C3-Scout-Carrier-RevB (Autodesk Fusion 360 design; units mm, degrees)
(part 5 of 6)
work_plane "WorkPlane1" AlongDistance 0.1 ExtraOffset 0
sketch "Component body profile" plane through (0, 0, 0.1) normal (0, 0, 1) x axis (1, 0, 0)
  line L1 (2.25, -1.4) -> (-2.25, -1.4)
  line L2 (2.25, 1.4) -> (2.25, -1.4)
  line L3 (-2.25, 1.4) -> (2.25, 1.4)
  line L4 (-2.25, -1.4) -> (-2.25, 1.4)
extrude "Extrude1" new body sketch "Component body profile" along normal blind 1.9
sketch "Metallized terminations profiles" plane through (0, 0, 0) normal (0, 0, 1) x axis (1, 0, 0)
  line L1 (-1.65, -1.4) -> (-2.3, -1.4)
  line L2 (-1.65, 1.4) -> (-1.65, -1.4)
  line L3 (-2.3, 1.4) -> (-1.65, 1.4)
  line L4 (-2.3, -1.4) -> (-2.3, 1.4)
  line L5 (2.3, -1.4) -> (1.65, -1.4)
  line L6 (2.3, 1.4) -> (2.3, -1.4)
  line L7 (1.65, 1.4) -> (2.3, 1.4)
  line L8 (1.65, -1.4) -> (1.65, 1.4)
extrude "Extrude2" new body sketch "Metallized terminations profiles" along normal blind 0.5
work_plane "WorkPlane2" AlongDistance 2 ExtraOffset 0
sketch "Cathode band profiles" plane through (0, 0, 2) normal (0, 0, 1) x axis (1, 0, 0)
  line L1 (-1.35, -1.4) -> (-1.65, -1.4)
  line L2 (-1.35, 1.4) -> (-1.35, -1.4)
  line L3 (-1.65, 1.4) -> (-1.35, 1.4)
  line L4 (-1.65, -1.4) -> (-1.65, 1.4)
extrude "Extrude3" new body sketch "Cathode band profiles" along normal blind 0.012
work_plane "WorkPlane1" AlongDistance 0.1 ExtraOffset 0
sketch "Component body profile" plane through (0, 0, 0.1) normal (0, 0, 1) x axis (1, 0, 0)
  line L1 (1.6, -0.8) -> (-1.6, -0.8)
  line L2 (1.6, 0.8) -> (1.6, -0.8)
  line L3 (-1.6, 0.8) -> (1.6, 0.8)
  line L4 (-1.6, -0.8) -> (-1.6, 0.8)
extrude "Extrude1" new body sketch "Component body profile" along normal blind 0.6
sketch "Metallized terminations profiles" plane through (0, 0, 0) normal (0, 0, 1) x axis (1, 0, 0)
  line L1 (-1.25, -0.8) -> (-1.65, -0.8)
  line L2 (-1.25, 0.8) -> (-1.25, -0.8)
  line L3 (-1.65, 0.8) -> (-1.25, 0.8)
  line L4 (-1.65, -0.8) -> (-1.65, 0.8)
  line L5 (1.65, -0.8) -> (1.25, -0.8)
  line L6 (1.65, 0.8) -> (1.65, -0.8)
  line L7 (1.25, 0.8) -> (1.65, 0.8)
  line L8 (1.25, -0.8) -> (1.25, 0.8)
extrude "Extrude2" new body sketch "Metallized terminations profiles" along normal blind 0.5
work_plane "WorkPlane1" AlongDistance 0.1 ExtraOffset 0
sketch "Component body profile" plane through (0, 0, 0.1) normal (0, 0, 1) x axis (1, 0, 0)
  line L1 (1.6, -0.8) -> (-1.6, -0.8)
  line L2 (1.6, 0.8) -> (1.6, -0.8)
  line L3 (-1.6, 0.8) -> (1.6, 0.8)
  line L4 (-1.6, -0.8) -> (-1.6, 0.8)
extrude "Extrude1" new body sketch "Component body profile" along normal blind 0.6
sketch "Metallized terminations profiles" plane through (0, 0, 0) normal (0, 0, 1) x axis (1, 0, 0)
  line L1 (-1.25, -0.8) -> (-1.65, -0.8)
  line L2 (-1.25, 0.8) -> (-1.25, -0.8)
  line L3 (-1.65, 0.8) -> (-1.25, 0.8)
  line L4 (-1.65, -0.8) -> (-1.65, 0.8)
  line L5 (1.65, -0.8) -> (1.25, -0.8)
  line L6 (1.65, 0.8) -> (1.65, -0.8)
  line L7 (1.25, 0.8) -> (1.65, 0.8)
  line L8 (1.25, -0.8) -> (1.25, 0.8)
extrude "Extrude2" new body sketch "Metallized terminations profiles" along normal blind 0.5
work_plane "WorkPlane1" AlongDistance 0.1 ExtraOffset 0
sketch "Component body profile" plane through (0, 0, 0.1) normal (0, 0, 1) x axis (1, 0, 0)
  line L1 (1.6, -0.8) -> (-1.6, -0.8)
  line L2 (1.6, 0.8) -> (1.6, -0.8)
  line L3 (-1.6, 0.8) -> (1.6, 0.8)
  line L4 (-1.6, -0.8) -> (-1.6, 0.8)
extrude "Extrude1" new body sketch "Component body profile" along normal blind 0.6
sketch "Metallized terminations profiles" plane through (0, 0, 0) normal (0, 0, 1) x axis (1, 0, 0)
  line L1 (-1.25, -0.8) -> (-1.65, -0.8)
  line L2 (-1.25, 0.8) -> (-1.25, -0.8)
  line L3 (-1.65, 0.8) -> (-1.25, 0.8)
  line L4 (-1.65, -0.8) -> (-1.65, 0.8)
  line L5 (1.65, -0.8) -> (1.25, -0.8)
  line L6 (1.65, 0.8) -> (1.65, -0.8)
  line L7 (1.25, 0.8) -> (1.65, 0.8)
  line L8 (1.25, -0.8) -> (1.25, 0.8)
extrude "Extrude2" new body sketch "Metallized terminations profiles" along normal blind 0.5
work_plane "WorkPlane1" AlongDistance 0.1 ExtraOffset 0
sketch "Component body profile" plane through (0, 0, 0.1) normal (0, 0, 1) x axis (1, 0, 0)
  line L1 (1, -0.625) -> (-1, -0.625)
  line L2 (1, 0.625) -> (1, -0.625)
  line L3 (-1, 0.625) -> (1, 0.625)
  line L4 (-1, -0.625) -> (-1, 0.625)
extrude "Extrude1" new body sketch "Component body profile" along normal blind 0.6
sketch "Metallized terminations profiles" plane through (0, 0, 0) normal (0, 0, 1) x axis (1, 0, 0)
  line L1 (-0.65, -0.625) -> (-1.05, -0.625)
  line L2 (-0.65, 0.625) -> (-0.65, -0.625)
  line L3 (-1.05, 0.625) -> (-0.65, 0.625)
  line L4 (-1.05, -0.625) -> (-1.05, 0.625)
  line L5 (1.05, -0.625) -> (0.65, -0.625)
  line L6 (1.05, 0.625) -> (1.05, -0.625)
  line L7 (0.65, 0.625) -> (1.05, 0.625)
  line L8 (0.65, -0.625) -> (0.65, 0.625)
extrude "Extrude2" new body sketch "Metallized terminations profiles" along normal blind 0.5
work_plane "WorkPlane1" AlongDistance 0.1 ExtraOffset 0
sketch "Component body profile" plane through (0, 0, 0.1) normal (0, 0, 1) x axis (1, 0, 0)
  line L1 (1, -0.625) -> (-1, -0.625)
  line L2 (1, 0.625) -> (1, -0.625)
  line L3 (-1, 0.625) -> (1, 0.625)
  line L4 (-1, -0.625) -> (-1, 0.625)
extrude "Extrude1" new body sketch "Component body profile" along normal blind 0.6
sketch "Metallized terminations profiles" plane through (0, 0, 0) normal (0, 0, 1) x axis (1, 0, 0)
  line L1 (-0.65, -0.625) -> (-1.05, -0.625)
  line L2 (-0.65, 0.625) -> (-0.65, -0.625)
  line L3 (-1.05, 0.625) -> (-0.65, 0.625)
  line L4 (-1.05, -0.625) -> (-1.05, 0.625)
  line L5 (1.05, -0.625) -> (0.65, -0.625)
  line L6 (1.05, 0.625) -> (1.05, -0.625)
  line L7 (0.65, 0.625) -> (1.05, 0.625)
  line L8 (0.65, -0.625) -> (0.65, 0.625)
extrude "Extrude2" new body sketch "Metallized terminations profiles" along normal blind 0.5
work_plane "WorkPlane1" AlongDistance 0.1 ExtraOffset 0
sketch "Component body profile" plane through (0, 0, 0.1) normal (0, 0, 1) x axis (1, 0, 0)
  line L1 (1, -0.625) -> (-1, -0.625)
  line L2 (1, 0.625) -> (1, -0.625)
  line L3 (-1, 0.625) -> (1, 0.625)
  line L4 (-1, -0.625) -> (-1, 0.625)
extrude "Extrude1" new body sketch "Component body profile" along normal blind 0.6
sketch "Metallized terminations profiles" plane through (0, 0, 0) normal (0, 0, 1) x axis (1, 0, 0)
  line L1 (-0.65, -0.625) -> (-1.05, -0.625)
  line L2 (-0.65, 0.625) -> (-0.65, -0.625)
  line L3 (-1.05, 0.625) -> (-0.65, 0.625)
  line L4 (-1.05, -0.625) -> (-1.05, 0.625)
  line L5 (1.05, -0.625) -> (0.65, -0.625)
  line L6 (1.05, 0.625) -> (1.05, -0.625)
  line L7 (0.65, 0.625) -> (1.05, 0.625)
  line L8 (0.65, -0.625) -> (0.65, 0.625)
extrude "Extrude2" new body sketch "Metallized terminations profiles" along normal blind 0.5
work_plane "WorkPlane1" AlongDistance 0.1 ExtraOffset 0
sketch "Component body profile" plane through (0, 0, 0.1) normal (0, 0, 1) x axis (1, 0, 0)
  line L1 (1, -0.625) -> (-1, -0.625)
  line L2 (1, 0.625) -> (1, -0.625)
  line L3 (-1, 0.625) -> (1, 0.625)
  line L4 (-1, -0.625) -> (-1, 0.625)
extrude "Extrude1" new body sketch "Component body profile" along normal blind 0.6
sketch "Metallized terminations profiles" plane through (0, 0, 0) normal (0, 0, 1) x axis (1, 0, 0)
  line L1 (-0.65, -0.625) -> (-1.05, -0.625)
  line L2 (-0.65, 0.625) -> (-0.65, -0.625)
  line L3 (-1.05, 0.625) -> (-0.65, 0.625)
  line L4 (-1.05, -0.625) -> (-1.05, 0.625)
  line L5 (1.05, -0.625) -> (0.65, -0.625)
  line L6 (1.05, 0.625) -> (1.05, -0.625)
  line L7 (0.65, 0.625) -> (1.05, 0.625)
  line L8 (0.65, -0.625) -> (0.65, 0.625)
extrude "Extrude2" new body sketch "Metallized terminations profiles" along normal blind 0.5
work_plane "WorkPlane1" AlongDistance 0.1 ExtraOffset 0
sketch "Component body profile" plane through (0, 0, 0.1) normal (0, 0, 1) x axis (1, 0, 0)
  line L1 (1, -0.625) -> (-1, -0.625)
  line L2 (1, 0.625) -> (1, -0.625)
  line L3 (-1, 0.625) -> (1, 0.625)
  line L4 (-1, -0.625) -> (-1, 0.625)
extrude "Extrude1" new body sketch "Component body profile" along normal blind 0.6
sketch "Metallized terminations profiles" plane through (0, 0, 0) normal (0, 0, 1) x axis (1, 0, 0)
  line L1 (-0.65, -0.625) -> (-1.05, -0.625)
  line L2 (-0.65, 0.625) -> (-0.65, -0.625)
  line L3 (-1.05, 0.625) -> (-0.65, 0.625)
  line L4 (-1.05, -0.625) -> (-1.05, 0.625)
  line L5 (1.05, -0.625) -> (0.65, -0.625)
  line L6 (1.05, 0.625) -> (1.05, -0.625)
  line L7 (0.65, 0.625) -> (1.05, 0.625)
  line L8 (0.65, -0.625) -> (0.65, 0.625)
extrude "Extrude2" new body sketch "Metallized terminations profiles" along normal blind 0.5
work_plane "WorkPlane1" AlongDistance 0.1 ExtraOffset 0
sketch "Component body profile" plane through (0, 0, 0.1) normal (0, 0, 1) x axis (1, 0, 0)
  line L1 (1, -0.625) -> (-1, -0.625)
  line L2 (1, 0.625) -> (1, -0.625)
  line L3 (-1, 0.625) -> (1, 0.625)
  line L4 (-1, -0.625) -> (-1, 0.625)
extrude "Extrude1" new body sketch "Component body profile" along normal blind 0.6
sketch "Metallized terminations profiles" plane through (0, 0, 0) normal (0, 0, 1) x axis (1, 0, 0)
  line L1 (-0.65, -0.625) -> (-1.05, -0.625)
  line L2 (-0.65, 0.625) -> (-0.65, -0.625)
  line L3 (-1.05, 0.625) -> (-0.65, 0.625)
  line L4 (-1.05, -0.625) -> (-1.05, 0.625)
  line L5 (1.05, -0.625) -> (0.65, -0.625)
  line L6 (1.05, 0.625) -> (1.05, -0.625)
  line L7 (0.65, 0.625) -> (1.05, 0.625)
  line L8 (0.65, -0.625) -> (0.65, 0.625)
extrude "Extrude2" new body sketch "Metallized terminations profiles" along normal blind 0.5
work_plane "WorkPlane1" AlongDistance 0.1 ExtraOffset 0
sketch "Component body profile" plane through (0, 0, 0.1) normal (0, 0, 1) x axis (1, 0, 0)
  line L1 (1, -0.625) -> (-1, -0.625)
  line L2 (1, 0.625) -> (1, -0.625)
  line L3 (-1, 0.625) -> (1, 0.625)
  line L4 (-1, -0.625) -> (-1, 0.625)
extrude "Extrude1" new body sketch "Component body profile" along normal blind 0.6
sketch "Metallized terminations profiles" plane through (0, 0, 0) normal (0, 0, 1) x axis (1, 0, 0)
  line L1 (-0.65, -0.625) -> (-1.05, -0.625)
  line L2 (-0.65, 0.625) -> (-0.65, -0.625)
  line L3 (-1.05, 0.625) -> (-0.65, 0.625)
  line L4 (-1.05, -0.625) -> (-1.05, 0.625)
  line L5 (1.05, -0.625) -> (0.65, -0.625)
  line L6 (1.05, 0.625) -> (1.05, -0.625)
  line L7 (0.65, 0.625) -> (1.05, 0.625)
  line L8 (0.65, -0.625) -> (0.65, 0.625)
extrude "Extrude2" new body sketch "Metallized terminations profiles" along normal blind 0.5
work_plane "WorkPlane1" AlongDistance 0.1 ExtraOffset 0
sketch "Component body profile" plane through (0, 0, 0.1) normal (0, 0, 1) x axis (1, 0, 0)
  line L1 (1, -0.625) -> (-1, -0.625)
  line L2 (1, 0.625) -> (1, -0.625)
  line L3 (-1, 0.625) -> (1, 0.625)
  line L4 (-1, -0.625) -> (-1, 0.625)
extrude "Extrude1" new body sketch "Component body profile" along normal blind 0.6
sketch "Metallized terminations profiles" plane through (0, 0, 0) normal (0, 0, 1) x axis (1, 0, 0)
  line L1 (-0.65, -0.625) -> (-1.05, -0.625)
  line L2 (-0.65, 0.625) -> (-0.65, -0.625)
  line L3 (-1.05, 0.625) -> (-0.65, 0.625)
  line L4 (-1.05, -0.625) -> (-1.05, 0.625)
  line L5 (1.05, -0.625) -> (0.65, -0.625)
  line L6 (1.05, 0.625) -> (1.05, -0.625)
  line L7 (0.65, 0.625) -> (1.05, 0.625)
  line L8 (0.65, -0.625) -> (0.65, 0.625)
extrude "Extrude2" new body sketch "Metallized terminations profiles" along normal blind 0.5
work_plane "WorkPlane1" AlongDistance 0.1 ExtraOffset 0
sketch "Component body profile" plane through (0, 0, 0.1) normal (0, 0, 1) x axis (1, 0, 0)
  line L1 (1, -0.625) -> (-1, -0.625)
  line L2 (1, 0.625) -> (1, -0.625)
  line L3 (-1, 0.625) -> (1, 0.625)
  line L4 (-1, -0.625) -> (-1, 0.625)
extrude "Extrude1" new body sketch "Component body profile" along normal blind 0.6
sketch "Metallized terminations profiles" plane through (0, 0, 0) normal (0, 0, 1) x axis (1, 0, 0)
  line L1 (-0.65, -0.625) -> (-1.05, -0.625)
  line L2 (-0.65, 0.625) -> (-0.65, -0.625)
  line L3 (-1.05, 0.625) -> (-0.65, 0.625)
  line L4 (-1.05, -0.625) -> (-1.05, 0.625)
  line L5 (1.05, -0.625) -> (0.65, -0.625)
  line L6 (1.05, 0.625) -> (1.05, -0.625)
  line L7 (0.65, 0.625) -> (1.05, 0.625)
  line L8 (0.65, -0.625) -> (0.65, 0.625)
extrude "Extrude2" new body sketch "Metallized terminations profiles" along normal blind 0.5
work_plane "WorkPlane1" AlongDistance 0.1 ExtraOffset 0
sketch "Component body profile" plane through (0, 0, 0.1) normal (0, 0, 1) x axis (1, 0, 0)
  line L1 (1, -0.625) -> (-1, -0.625)
  line L2 (1, 0.625) -> (1, -0.625)
  line L3 (-1, 0.625) -> (1, 0.625)
  line L4 (-1, -0.625) -> (-1, 0.625)
extrude "Extrude1" new body sketch "Component body profile" along normal blind 0.6
sketch "Metallized terminations profiles" plane through (0, 0, 0) normal (0, 0, 1) x axis (1, 0, 0)
  line L1 (-0.65, -0.625) -> (-1.05, -0.625)
  line L2 (-0.65, 0.625) -> (-0.65, -0.625)
  line L3 (-1.05, 0.625) -> (-0.65, 0.625)
  line L4 (-1.05, -0.625) -> (-1.05, 0.625)
  line L5 (1.05, -0.625) -> (0.65, -0.625)
  line L6 (1.05, 0.625) -> (1.05, -0.625)
  line L7 (0.65, 0.625) -> (1.05, 0.625)
  line L8 (0.65, -0.625) -> (0.65, 0.625)
extrude "Extrude2" new body sketch "Metallized terminations profiles" along normal blind 0.5
work_plane "WorkPlane1" AlongDistance 0.1 ExtraOffset 0
sketch "Component body profile" plane through (0, 0, 0.1) normal (0, 0, 1) x axis (1, 0, 0)
  line L1 (1, -0.625) -> (-1, -0.625)
  line L2 (1, 0.625) -> (1, -0.625)
  line L3 (-1, 0.625) -> (1, 0.625)
  line L4 (-1, -0.625) -> (-1, 0.625)
extrude "Extrude1" new body sketch "Component body profile" along normal blind 0.6
sketch "Metallized terminations profiles" plane through (0, 0, 0) normal (0, 0, 1) x axis (1, 0, 0)
  line L1 (-0.65, -0.625) -> (-1.05, -0.625)
  line L2 (-0.65, 0.625) -> (-0.65, -0.625)
  line L3 (-1.05, 0.625) -> (-0.65, 0.625)
  line L4 (-1.05, -0.625) -> (-1.05, 0.625)
  line L5 (1.05, -0.625) -> (0.65, -0.625)
  line L6 (1.05, 0.625) -> (1.05, -0.625)
  line L7 (0.65, 0.625) -> (1.05, 0.625)
  line L8 (0.65, -0.625) -> (0.65, 0.625)
extrude "Extrude2" new body sketch "Metallized terminations profiles" along normal blind 0.5
work_plane "WorkPlane1" AlongDistance 0.1 ExtraOffset 0
sketch "Component body profile" plane through (0, 0, 0.1) normal (0, 0, 1) x axis (1, 0, 0)
  line L1 (1, -0.625) -> (-1, -0.625)
  line L2 (1, 0.625) -> (1, -0.625)
  line L3 (-1, 0.625) -> (1, 0.625)
  line L4 (-1, -0.625) -> (-1, 0.625)
extrude "Extrude1" new body sketch "Component body profile" along normal blind 0.6
sketch "Metallized terminations profiles" plane through (0, 0, 0) normal (0, 0, 1) x axis (1, 0, 0)
  line L1 (-0.65, -0.625) -> (-1.05, -0.625)
  line L2 (-0.65, 0.625) -> (-0.65, -0.625)
  line L3 (-1.05, 0.625) -> (-0.65, 0.625)
  line L4 (-1.05, -0.625) -> (-1.05, 0.625)
  line L5 (1.05, -0.625) -> (0.65, -0.625)
  line L6 (1.05, 0.625) -> (1.05, -0.625)
  line L7 (0.65, 0.625) -> (1.05, 0.625)
  line L8 (0.65, -0.625) -> (0.65, 0.625)
extrude "Extrude2" new body sketch "Metallized terminations profiles" along normal blind 0.5
work_plane "WorkPlane1" AlongDistance 0.1 ExtraOffset 0
sketch "Component body profile" plane through (0, 0, 0.1) normal (0, 0, 1) x axis (1, 0, 0)
  line L1 (1, -0.625) -> (-1, -0.625)
  line L2 (1, 0.625) -> (1, -0.625)
  line L3 (-1, 0.625) -> (1, 0.625)
  line L4 (-1, -0.625) -> (-1, 0.625)
extrude "Extrude1" new body sketch "Component body profile" along normal blind 0.6
sketch "Metallized terminations profiles" plane through (0, 0, 0) normal (0, 0, 1) x axis (1, 0, 0)
  line L1 (-0.65, -0.625) -> (-1.05, -0.625)
  line L2 (-0.65, 0.625) -> (-0.65, -0.625)
  line L3 (-1.05, 0.625) -> (-0.65, 0.625)
  line L4 (-1.05, -0.625) -> (-1.05, 0.625)
  line L5 (1.05, -0.625) -> (0.65, -0.625)
  line L6 (1.05, 0.625) -> (1.05, -0.625)
  line L7 (0.65, 0.625) -> (1.05, 0.625)
  line L8 (0.65, -0.625) -> (0.65, 0.625)
extrude "Extrude2" new body sketch "Metallized terminations profiles" along normal blind 0.5
work_plane "WorkPlane1" AlongDistance 0.1 ExtraOffset 0
sketch "Component body profile" plane through (0, 0, 0.1) normal (0, 0, 1) x axis (1, 0, 0)
  line L1 (1, -0.625) -> (-1, -0.625)
  line L2 (1, 0.625) -> (1, -0.625)
  line L3 (-1, 0.625) -> (1, 0.625)
  line L4 (-1, -0.625) -> (-1, 0.625)
extrude "Extrude1" new body sketch "Component body profile" along normal blind 0.6
sketch "Metallized terminations profiles" plane through (0, 0, 0) normal (0, 0, 1) x axis (1, 0, 0)
  line L1 (-0.65, -0.625) -> (-1.05, -0.625)
  line L2 (-0.65, 0.625) -> (-0.65, -0.625)
  line L3 (-1.05, 0.625) -> (-0.65, 0.625)
  line L4 (-1.05, -0.625) -> (-1.05, 0.625)
  line L5 (1.05, -0.625) -> (0.65, -0.625)
  line L6 (1.05, 0.625) -> (1.05, -0.625)
  line L7 (0.65, 0.625) -> (1.05, 0.625)
  line L8 (0.65, -0.625) -> (0.65, 0.625)
extrude "Extrude2" new body sketch "Metallized terminations profiles" along normal blind 0.5
work_plane "WorkPlane1" AlongDistance 0.1 ExtraOffset 0
sketch "Component body profile" plane through (0, 0, 0.1) normal (0, 0, 1) x axis (1, 0, 0)
  line L1 (1, -0.625) -> (-1, -0.625)
  line L2 (1, 0.625) -> (1, -0.625)
  line L3 (-1, 0.625) -> (1, 0.625)
  line L4 (-1, -0.625) -> (-1, 0.625)
extrude "Extrude1" new body sketch "Component body profile" along normal blind 0.6
sketch "Metallized terminations profiles" plane through (0, 0, 0) normal (0, 0, 1) x axis (1, 0, 0)
  line L1 (-0.65, -0.625) -> (-1.05, -0.625)
  line L2 (-0.65, 0.625) -> (-0.65, -0.625)
  line L3 (-1.05, 0.625) -> (-0.65, 0.625)
  line L4 (-1.05, -0.625) -> (-1.05, 0.625)
  line L5 (1.05, -0.625) -> (0.65, -0.625)
  line L6 (1.05, 0.625) -> (1.05, -0.625)
  line L7 (0.65, 0.625) -> (1.05, 0.625)
  line L8 (0.65, -0.625) -> (0.65, 0.625)
extrude "Extrude2" new body sketch "Metallized terminations profiles" along normal blind 0.5
work_plane "WorkPlane1" AlongDistance 0.1 ExtraOffset 0
sketch "Component body profile" plane through (0, 0, 0.1) normal (0, 0, 1) x axis (1, 0, 0)
  line L1 (1, -0.625) -> (-1, -0.625)
  line L2 (1, 0.625) -> (1, -0.625)
  line L3 (-1, 0.625) -> (1, 0.625)
  line L4 (-1, -0.625) -> (-1, 0.625)
extrude "Extrude1" new body sketch "Component body profile" along normal blind 0.6
sketch "Metallized terminations profiles" plane through (0, 0, 0) normal (0, 0, 1) x axis (1, 0, 0)
  line L1 (-0.65, -0.625) -> (-1.05, -0.625)
  line L2 (-0.65, 0.625) -> (-0.65, -0.625)
  line L3 (-1.05, 0.625) -> (-0.65, 0.625)
  line L4 (-1.05, -0.625) -> (-1.05, 0.625)
  line L5 (1.05, -0.625) -> (0.65, -0.625)
  line L6 (1.05, 0.625) -> (1.05, -0.625)
  line L7 (0.65, 0.625) -> (1.05, 0.625)
  line L8 (0.65, -0.625) -> (0.65, 0.625)
extrude "Extrude2" new body sketch "Metallized terminations profiles" along normal blind 0.5
work_plane "WorkPlane1" AlongDistance 0.1 ExtraOffset 0
sketch "Component body profile" plane through (0, 0, 0.1) normal (0, 0, 1) x axis (1, 0, 0)
  line L1 (1.6, -0.8) -> (-1.6, -0.8)
  line L2 (1.6, 0.8) -> (1.6, -0.8)
  line L3 (-1.6, 0.8) -> (1.6, 0.8)
  line L4 (-1.6, -0.8) -> (-1.6, 0.8)
extrude "Extrude1" new body sketch "Component body profile" along normal blind 0.6
sketch "Metallized terminations profiles" plane through (0, 0, 0) normal (0, 0, 1) x axis (1, 0, 0)
  line L1 (-1.25, -0.8) -> (-1.65, -0.8)
  line L2 (-1.25, 0.8) -> (-1.25, -0.8)
  line L3 (-1.65, 0.8) -> (-1.25, 0.8)
  line L4 (-1.65, -0.8) -> (-1.65, 0.8)
  line L5 (1.65, -0.8) -> (1.25, -0.8)
  line L6 (1.65, 0.8) -> (1.65, -0.8)
  line L7 (1.25, 0.8) -> (1.65, 0.8)
  line L8 (1.25, -0.8) -> (1.25, 0.8)
extrude "Extrude2" new body sketch "Metallized terminations profiles" along normal blind 0.5
sketch "Header insulators profiles" plane through (0, 0, 0) normal (0, 0, 1) x axis (1, 0, 0)
  line L1 (-6.42, -10.16) -> (-8.82, -10.16)
  line L2 (-6.42, 10.16) -> (-6.42, -10.16)
  line L3 (-8.82, 10.16) -> (-6.42, 10.16)
  line L4 (-8.82, -10.16) -> (-8.82, 10.16)
  line L5 (8.82, -10.16) -> (6.42, -10.16)
  line L6 (8.82, 10.16) -> (8.82, -10.16)
  line L7 (6.42, 10.16) -> (8.82, 10.16)
  line L8 (6.42, -10.16) -> (6.42, 10.16)
extrude "Extrude1" new body sketch "Header insulators profiles" along normal blind 2.5
work_plane "WorkPlane1" AlongDistance -2 ExtraOffset 0
sketch "Sixteen soldered square pins profiles" plane through (0, 0, -2) normal (0, 0, 1) x axis (1, 0, 0)
  line L1 (-7.37, 8.64) -> (-7.87, 8.64)
  line L2 (-7.37, 9.14) -> (-7.37, 8.64)
  line L3 (-7.87, 9.14) -> (-7.37, 9.14)
  line L4 (-7.87, 8.64) -> (-7.87, 9.14)
  line L5 (-7.37, 6.1) -> (-7.87, 6.1)
  line L6 (-7.37, 6.6) -> (-7.37, 6.1)
  line L7 (-7.87, 6.6) -> (-7.37, 6.6)
  line L8 (-7.87, 6.1) -> (-7.87, 6.6)
  line L9 (-7.37, 3.56) -> (-7.87, 3.56)
  line L10 (-7.37, 4.06) -> (-7.37, 3.56)
  line L11 (-7.87, 4.06) -> (-7.37, 4.06)
  line L12 (-7.87, 3.56) -> (-7.87, 4.06)
  line L13 (-7.37, 1.02) -> (-7.87, 1.02)
  line L14 (-7.37, 1.52) -> (-7.37, 1.02)
  line L15 (-7.87, 1.52) -> (-7.37, 1.52)
  line L16 (-7.87, 1.02) -> (-7.87, 1.52)
  line L17 (-7.37, -1.52) -> (-7.87, -1.52)
  line L18 (-7.37, -1.02) -> (-7.37, -1.52)
  line L19 (-7.87, -1.02) -> (-7.37, -1.02)
  line L20 (-7.87, -1.52) -> (-7.87, -1.02)
  line L21 (-7.37, -4.06) -> (-7.87, -4.06)
  line L22 (-7.37, -3.56) -> (-7.37, -4.06)
  line L23 (-7.87, -3.56) -> (-7.37, -3.56)
  line L24 (-7.87, -4.06) -> (-7.87, -3.56)
  line L25 (-7.37, -6.6) -> (-7.87, -6.6)
  line L26 (-7.37, -6.1) -> (-7.37, -6.6)
  line L27 (-7.87, -6.1) -> (-7.37, -6.1)
  line L28 (-7.87, -6.6) -> (-7.87, -6.1)
  line L29 (-7.37, -9.14) -> (-7.87, -9.14)
  line L30 (-7.37, -8.64) -> (-7.37, -9.14)
  line L31 (-7.87, -8.64) -> (-7.37, -8.64)
  line L32 (-7.87, -9.14) -> (-7.87, -8.64)
  line L33 (7.87, 8.64) -> (7.37, 8.64)
  line L34 (7.87, 9.14) -> (7.87, 8.64)
  line L35 (7.37, 9.14) -> (7.87, 9.14)
  line L36 (7.37, 8.64) -> (7.37, 9.14)
  line L37 (7.87, 6.1) -> (7.37, 6.1)
  line L38 (7.87, 6.6) -> (7.87, 6.1)
  line L39 (7.37, 6.6) -> (7.87, 6.6)
  line L40 (7.37, 6.1) -> (7.37, 6.6)
  line L41 (7.87, 3.56) -> (7.37, 3.56)
  line L42 (7.87, 4.06) -> (7.87, 3.56)
  line L43 (7.37, 4.06) -> (7.87, 4.06)
  line L44 (7.37, 3.56) -> (7.37, 4.06)
  line L45 (7.87, 1.02) -> (7.37, 1.02)
  line L46 (7.87, 1.52) -> (7.87, 1.02)
  line L47 (7.37, 1.52) -> (7.87, 1.52)
  line L48 (7.37, 1.02) -> (7.37, 1.52)
  line L49 (7.87, -1.52) -> (7.37, -1.52)
  line L50 (7.87, -1.02) -> (7.87, -1.52)
  line L51 (7.37, -1.02) -> (7.87, -1.02)
  line L52 (7.37, -1.52) -> (7.37, -1.02)
  line L53 (7.87, -4.06) -> (7.37, -4.06)
  line L54 (7.87, -3.56) -> (7.87, -4.06)
  line L55 (7.37, -3.56) -> (7.87, -3.56)
  line L56 (7.37, -4.06) -> (7.37, -3.56)
  line L57 (7.87, -6.6) -> (7.37, -6.6)
  line L58 (7.87, -6.1) -> (7.87, -6.6)
  line L59 (7.37, -6.1) -> (7.87, -6.1)
  line L60 (7.37, -6.6) -> (7.37, -6.1)
  line L61 (7.87, -9.14) -> (7.37, -9.14)
  line L62 (7.87, -8.64) -> (7.87, -9.14)
  line L63 (7.37, -8.64) -> (7.87, -8.64)
  line L64 (7.37, -9.14) -> (7.37, -8.64)
extrude "Extrude2" new body sketch "Sixteen soldered square pins profiles" along normal blind 6.2
sketch "Chamfered adhesive foot outline" plane through (0, 0, 0) normal (0, 0, 1) x axis (1, 0, 0)
  line L1 (31, -1.8) -> (1, -1.8)
  line L2 (32, -0.8) -> (31, -1.8)
  line L3 (32, 0.8) -> (32, -0.8)
  line L4 (31, 1.8) -> (32, 0.8)
  line L5 (1, 1.8) -> (31, 1.8)
  line L6 (0, 0.8) -> (1, 1.8)
  line L7 (0, -0.8) -> (0, 0.8)
  line L8 (1, -1.8) -> (0, -0.8)
extrude "Extrude1" new body sketch "Chamfered adhesive foot outline" along normal blind 1.2
work_plane "WorkPlane1" AlongDistance 1.2 ExtraOffset 0
sketch "M2 support boss profile" plane through (0, 0, 1.2) normal (0, 0, 1) x axis (1, 0, 0)
  circle C1 centre (3, 0) radius 2.8
extrude "Extrude2" add sketch "M2 support boss profile" along normal blind 4.3
work_plane "WorkPlane2" AlongDistance 1.2 ExtraOffset 0
sketch "M2 support boss profile (1)" plane through (0, 0, 1.2) normal (0, 0, 1) x axis (1, 0, 0)
  circle C1 centre (29, 0) radius 2.8
extrude "Extrude3" add sketch "M2 support boss profile (1)" along normal blind 4.3
sketch "M2 screw pilot holes profile" plane through (0, 0, 0) normal (0, 0, 1) x axis (1, 0, 0)
  circle C1 centre (3, 0) radius 0.85
  circle C2 centre (29, 0) radius 0.85
extrude "Extrude4" cut sketch "M2 screw pilot holes profile" along normal blind 5.5
sketch "M2 screw shank profile" plane through (0, 0, 0) normal (0, 0, 1) x axis (1, 0, 0)
  circle C1 centre (3, 0) radius 0.85
extrude "Extrude1" new body sketch "M2 screw shank profile" along normal blind 5.2
work_plane "WorkPlane1" AlongDistance 5.2 ExtraOffset 0
sketch "M2 pan head profile" plane through (0, 0, 5.2) normal (0, 0, 1) x axis (1, 0, 0)
  circle C1 centre (3, 0) radius 1.8
extrude "Extrude2" new body sketch "M2 pan head profile" along normal blind 1.2
work_plane "WorkPlane2" AlongDistance 5.95 ExtraOffset 0
sketch "Driver slot profile" plane through (0, 0, 5.95) normal (0, 0, 1) x axis (1, 0, 0)
  line L1 (4.1, -0.25) -> (1.9, -0.25)
  line L2 (4.1, 0.25) -> (4.1, -0.25)
  line L3 (1.9, 0.25) -> (4.1, 0.25)
  line L4 (1.9, -0.25) -> (1.9, 0.25)
extrude "Extrude3" cut sketch "Driver slot profile" along normal blind 0.46
sketch "M2 screw shank profile (1)" plane through (0, 0, 0) normal (0, 0, 1) x axis (1, 0, 0)
  circle C1 centre (29, 0) radius 0.85
extrude "Extrude4" new body sketch "M2 screw shank profile (1)" along normal blind 5.2
work_plane "WorkPlane3" AlongDistance 5.2 ExtraOffset 0
sketch "M2 pan head profile (1)" plane through (0, 0, 5.2) normal (0, 0, 1) x axis (1, 0, 0)
  circle C1 centre (29, 0) radius 1.8
extrude "Extrude5" new body sketch "M2 pan head profile (1)" along normal blind 1.2
work_plane "WorkPlane4" AlongDistance 5.95 ExtraOffset 0
sketch "Driver slot profile (1)" plane through (0, 0, 5.95) normal (0, 0, 1) x axis (1, 0, 0)
  line L1 (30.1, -0.25) -> (27.9, -0.25)
  line L2 (30.1, 0.25) -> (30.1, -0.25)
  line L3 (27.9, 0.25) -> (30.1, 0.25)
  line L4 (27.9, -0.25) -> (27.9, 0.25)
extrude "Extrude6" cut sketch "Driver slot profile (1)" along normal blind 0.46
sketch "Chamfered adhesive foot outline" plane through (0, 0, 0) normal (0, 0, 1) x axis (1, 0, 0)
  line L1 (31, -1.8) -> (1, -1.8)
  line L2 (32, -0.8) -> (31, -1.8)
  line L3 (32, 0.8) -> (32, -0.8)
  line L4 (31, 1.8) -> (32, 0.8)
  line L5 (1, 1.8) -> (31, 1.8)
  line L6 (0, 0.8) -> (1, 1.8)
  line L7 (0, -0.8) -> (0, 0.8)
  line L8 (1, -1.8) -> (0, -0.8)
extrude "Extrude1" new body sketch "Chamfered adhesive foot outline" along normal blind 1.2
work_plane "WorkPlane1" AlongDistance 1.2 ExtraOffset 0
sketch "M2 support boss profile" plane through (0, 0, 1.2) normal (0, 0, 1) x axis (1, 0, 0)
  circle C1 centre (3, 0) radius 2.8
extrude "Extrude2" add sketch "M2 support boss profile" along normal blind 4.3
work_plane "WorkPlane2" AlongDistance 1.2 ExtraOffset 0
sketch "M2 support boss profile (1)" plane through (0, 0, 1.2) normal (0, 0, 1) x axis (1, 0, 0)
  circle C1 centre (29, 0) radius 2.8
extrude "Extrude3" add sketch "M2 support boss profile (1)" along normal blind 4.3
sketch "M2 screw pilot holes profile" plane through (0, 0, 0) normal (0, 0, 1) x axis (1, 0, 0)
  circle C1 centre (3, 0) radius 0.85
  circle C2 centre (29, 0) radius 0.85
extrude "Extrude4" cut sketch "M2 screw pilot holes profile" along normal blind 5.5
sketch "M2 screw shank profile" plane through (0, 0, 0) normal (0, 0, 1) x axis (1, 0, 0)
  circle C1 centre (3, 0) radius 0.85
extrude "Extrude1" new body sketch "M2 screw shank profile" along normal blind 5.2
work_plane "WorkPlane1" AlongDistance 5.2 ExtraOffset 0
sketch "M2 pan head profile" plane through (0, 0, 5.2) normal (0, 0, 1) x axis (1, 0, 0)
  circle C1 centre (3, 0) radius 1.8
extrude "Extrude2" new body sketch "M2 pan head profile" along normal blind 1.2
work_plane "WorkPlane2" AlongDistance 5.95 ExtraOffset 0
sketch "Driver slot profile" plane through (0, 0, 5.95) normal (0, 0, 1) x axis (1, 0, 0)
  line L1 (4.1, -0.25) -> (1.9, -0.25)
  line L2 (4.1, 0.25) -> (4.1, -0.25)
  line L3 (1.9, 0.25) -> (4.1, 0.25)
  line L4 (1.9, -0.25) -> (1.9, 0.25)
extrude "Extrude3" cut sketch "Driver slot profile" along normal blind 0.46
sketch "M2 screw shank profile (1)" plane through (0, 0, 0) normal (0, 0, 1) x axis (1, 0, 0)
  circle C1 centre (29, 0) radius 0.85
extrude "Extrude4" new body sketch "M2 screw shank profile (1)" along normal blind 5.2
work_plane "WorkPlane3" AlongDistance 5.2 ExtraOffset 0
sketch "M2 pan head profile (1)" plane through (0, 0, 5.2) normal (0, 0, 1) x axis (1, 0, 0)
  circle C1 centre (29, 0) radius 1.8
extrude "Extrude5" new body sketch "M2 pan head profile (1)" along normal blind 1.2
work_plane "WorkPlane4" AlongDistance 5.95 ExtraOffset 0
sketch "Driver slot profile (1)" plane through (0, 0, 5.95) normal (0, 0, 1) x axis (1, 0, 0)
  line L1 (30.1, -0.25) -> (27.9, -0.25)
  line L2 (30.1, 0.25) -> (30.1, -0.25)
  line L3 (27.9, 0.25) -> (30.1, 0.25)
  line L4 (27.9, -0.25) -> (27.9, 0.25)
extrude "Extrude6" cut sketch "Driver slot profile (1)" along normal blind 0.46
position "Position5"
position "Position6"
work_plane "WorkPlane25" AlongDistance 4.5 ExtraOffset 0
sketch "Carrier rear rail relief widened profile" plane through (0, 0, 4.5) normal (0, 0, 1) x axis (1, 0, 0)
  line L1 (34, 60) -> (26.5, 60)
  line L2 (34, 66) -> (34, 60)
  line L3 (26.5, 66) -> (34, 66)
  line L4 (26.5, 60) -> (26.5, 66)
extrude "Extrude45" cut sketch "Carrier rear rail relief widened profile" along normal blind 4
sketch "Tail skid screw head clearance profile" plane through (0, 0, 0) normal (0, 0, 1) x axis (1, 0, 0)
  circle C1 centre (0.5, -3) radius 3.2
extrude "Extrude5" cut sketch "Tail skid screw head clearance profile" along normal blind 1.2
position "Position7"
sketch "Continuous sculpted chassis floor outline" plane through (0, 0, 0) normal (0, 0, 1) x axis (1, 0, 0)
  line L1 (30, -53) -> (-30, -53)
  line L2 (38, -43) -> (30, -53)
  line L3 (38, -19) -> (38, -43)
  line L4 (38, -12) -> (38, -19)
  line L5 (40.9, -8) -> (38, -12)
  line L6 (40.9, 67.4) -> (40.9, -8)
  line L7 (36.9, 71.4) -> (40.9, 67.4)
  line L8 (-28, 68) -> (36.9, 71.4)
  line L9 (-36, 50) -> (-28, 68)
  line L10 (-36, -8) -> (-36, 50)
  line L11 (-38, -19) -> (-36, -8)
  line L12 (-38, -43) -> (-38, -19)
  line L13 (-30, -53) -> (-38, -43)
extrude "Extrude1" new body sketch "Continuous sculpted chassis floor outline" along normal blind 3
fillet "Fillet1" radius 1.5
sketch "Battery ladder window 1 outline" plane through (0, 0, 0) normal (0, 0, 1) x axis (1, 0, 0)
  line L1 (-7, -12) -> (-25, -12)
  line L2 (-7, -2) -> (-7, -12)
  line L3 (-10, 0) -> (-7, -2)
  line L4 (-25, 0) -> (-10, 0)
  line L5 (-25, -12) -> (-25, 0)
extrude "Extrude2" cut sketch "Battery ladder window 1 outline" along normal blind 3
sketch "Battery ladder window 2 outline" plane through (0, 0, 0) normal (0, 0, 1) x axis (1, 0, 0)
  line L1 (-7, 11) -> (-25, 11)
  line L2 (-7, 24) -> (-7, 11)
  line L3 (-10, 26) -> (-7, 24)
  line L4 (-25, 26) -> (-10, 26)
  line L5 (-25, 11) -> (-25, 26)
extrude "Extrude3" cut sketch "Battery ladder window 2 outline" along normal blind 3
sketch "Battery ladder window 3 outline" plane through (0, 0, 0) normal (0, 0, 1) x axis (1, 0, 0)
  line L1 (-7, 29) -> (-25, 29)
  line L2 (-7, 34) -> (-7, 29)
  line L3 (-10, 36) -> (-7, 34)
  line L4 (-25, 36) -> (-10, 36)
  line L5 (-25, 29) -> (-25, 36)
extrude "Extrude4" cut sketch "Battery ladder window 3 outline" along normal blind 3
sketch "Battery ladder window 4 outline" plane through (0, 0, 0) normal (0, 0, 1) x axis (1, 0, 0)
  line L1 (-7, 47) -> (-25, 47)
  line L2 (-7, 58) -> (-7, 47)
  line L3 (-10, 60) -> (-7, 58)
  line L4 (-25, 60) -> (-10, 60)
  line L5 (-25, 47) -> (-25, 60)
extrude "Extrude5" cut sketch "Battery ladder window 4 outline" along normal blind 3
sketch "Carrier service window 1 outline" plane through (0, 0, 0) normal (0, 0, 1) x axis (1, 0, 0)
  line L1 (29, 0) -> (16, 0)
  line L2 (31, 2) -> (29, 0)
  line L3 (31, 12) -> (31, 2)
  line L4 (29, 14) -> (31, 12)
  line L5 (16, 14) -> (29, 14)
  line L6 (14, 12) -> (16, 14)
  line L7 (14, 2) -> (14, 12)
  line L8 (16, 0) -> (14, 2)
extrude "Extrude6" cut sketch "Carrier service window 1 outline" along normal blind 3
sketch "Carrier service window 2 outline" plane through (0, 0, 0) normal (0, 0, 1) x axis (1, 0, 0)
  line L1 (29, 21) -> (16, 21)
  line L2 (31, 23) -> (29, 21)
  line L3 (31, 33) -> (31, 23)
  line L4 (29, 35) -> (31, 33)
  line L5 (16, 35) -> (29, 35)
  line L6 (14, 33) -> (16, 35)
  line L7 (14, 23) -> (14, 33)
  line L8 (16, 21) -> (14, 23)
extrude "Extrude7" cut sketch "Carrier service window 2 outline" along normal blind 3
sketch "Carrier service window 3 outline" plane through (0, 0, 0) normal (0, 0, 1) x axis (1, 0, 0)
  line L1 (29, 43) -> (16, 43)
  line L2 (31, 45) -> (29, 43)
  line L3 (31, 53) -> (31, 45)
  line L4 (29, 55) -> (31, 53)
  line L5 (16, 55) -> (29, 55)
  line L6 (14, 53) -> (16, 55)
  line L7 (14, 45) -> (14, 53)
  line L8 (16, 43) -> (14, 45)
extrude "Extrude8" cut sketch "Carrier service window 3 outline" along normal blind 3
work_plane "WorkPlane1" AlongDistance 3 ExtraOffset 0
sketch "Port sculpted rail outline" plane through (0, 0, 3) normal (0, 0, 1) x axis (1, 0, 0)
  line L1 (-36, -14) -> (-33.8, -14)
  line L2 (-36, 49) -> (-36, -14)
  line L3 (-29, 64) -> (-36, 49)
  line L4 (-27, 64) -> (-29, 64)
  line L5 (-33.8, 48) -> (-27, 64)
  line L6 (-33.8, -14) -> (-33.8, 48)
extrude "Extrude9" add sketch "Port sculpted rail outline" along normal blind 4.5
work_plane "WorkPlane2" AlongDistance 3 ExtraOffset 0
sketch "Battery cradle rails profiles" plane through (0, 0, 3) normal (0, 0, 1) x axis (1, 0, 0)
  line L1 (-28, -17) -> (-30, -17)
  line L2 (-28, 65) -> (-28, -17)
  line L3 (-30, 65) -> (-28, 65)
  line L4 (-30, -17) -> (-30, 65)
  line L5 (-2, -17) -> (-4, -17)
  line L6 (-2, 65) -> (-2, -17)
  line L7 (-4, 65) -> (-2, 65)
  line L8 (-4, -17) -> (-4, 65)
  line L9 (-2, -18) -> (-30, -18)
  line L10 (-2, -16) -> (-2, -18)
  line L11 (-30, -16) -> (-2, -16)
  line L12 (-30, -18) -> (-30, -16)
  line L13 (-2, 64) -> (-30, 64)
  line L14 (-2, 66) -> (-2, 64)
  line L15 (-30, 66) -> (-2, 66)
  line L16 (-30, 64) -> (-30, 66)
extrude "Extrude10" add sketch "Battery cradle rails profiles" along normal blind 4.5
work_plane "WorkPlane3" AlongDistance 3 ExtraOffset 0
sketch "Motor seating pads profiles" plane through (0, 0, 3) normal (0, 0, 1) x axis (1, 0, 0)
  line L1 (-13, -37.8) -> (-37, -37.8)
  line L2 (-13, -26.2) -> (-13, -37.8)
  line L3 (-37, -26.2) -> (-13, -26.2)
  line L4 (-37, -37.8) -> (-37, -26.2)
  line L5 (37, -37.8) -> (13, -37.8)
  line L6 (37, -26.2) -> (37, -37.8)
  line L7 (13, -26.2) -> (37, -26.2)
  line L8 (13, -37.8) -> (13, -26.2)
extrude "Extrude11" add sketch "Motor seating pads profiles" along normal blind 0.4
work_plane "WorkPlane4" AlongDistance 3 ExtraOffset 0
sketch "Motor locating fences profiles" plane through (0, 0, 3) normal (0, 0, 1) x axis (1, 0, 0)
  line L1 (-31.4, -40.1) -> (-37, -40.1)
  line L2 (-31.4, -38.2) -> (-31.4, -40.1)
  line L3 (-37, -38.2) -> (-31.4, -38.2)
  line L4 (-37, -40.1) -> (-37, -38.2)
  line L5 (-31.4, -25.8) -> (-37, -25.8)
  line L6 (-31.4, -23.9) -> (-31.4, -25.8)
  line L7 (-37, -23.9) -> (-31.4, -23.9)
  line L8 (-37, -25.8) -> (-37, -23.9)
  line L9 (-13, -40.1) -> (-20.6, -40.1)
  line L10 (-13, -38.2) -> (-13, -40.1)
  line L11 (-20.6, -38.2) -> (-13, -38.2)
  line L12 (-20.6, -40.1) -> (-20.6, -38.2)
  line L13 (-13, -25.8) -> (-20.6, -25.8)
  line L14 (-13, -23.9) -> (-13, -25.8)
  line L15 (-20.6, -23.9) -> (-13, -23.9)
  line L16 (-20.6, -25.8) -> (-20.6, -23.9)
  line L17 (20.6, -40.1) -> (13, -40.1)
  line L18 (20.6, -38.2) -> (20.6, -40.1)
  line L19 (13, -38.2) -> (20.6, -38.2)
  line L20 (13, -40.1) -> (13, -38.2)
  line L21 (20.6, -25.8) -> (13, -25.8)
  line L22 (20.6, -23.9) -> (20.6, -25.8)
  line L23 (13, -23.9) -> (20.6, -23.9)
  line L24 (13, -25.8) -> (13, -23.9)
  line L25 (37, -40.1) -> (31.4, -40.1)
  line L26 (37, -38.2) -> (37, -40.1)
  line L27 (31.4, -38.2) -> (37, -38.2)
  line L28 (31.4, -40.1) -> (31.4, -38.2)
  line L29 (37, -25.8) -> (31.4, -25.8)
  line L30 (37, -23.9) -> (37, -25.8)
  line L31 (31.4, -23.9) -> (37, -23.9)
  line L32 (31.4, -25.8) -> (31.4, -23.9)
extrude "Extrude12" add sketch "Motor locating fences profiles" along normal blind 2.8
sketch "Battery strap passages profiles" plane through (0, 0, 0) normal (0, 0, 1) x axis (1, 0, 0)
  line L1 (-30.8, 1) -> (-33, 1)
  line L2 (-30.8, 9) -> (-30.8, 1)
  line L3 (-33, 9) -> (-30.8, 9)
  line L4 (-33, 1) -> (-33, 9)
  line L5 (-30.8, 37) -> (-33, 37)
  line L6 (-30.8, 45) -> (-30.8, 37)
  line L7 (-33, 45) -> (-30.8, 45)
  line L8 (-33, 37) -> (-33, 45)
  line L9 (1.4, 1) -> (-0.8, 1)
  line L10 (1.4, 9) -> (1.4, 1)
  line L11 (-0.8, 9) -> (1.4, 9)
  line L12 (-0.8, 1) -> (-0.8, 9)
  line L13 (1.4, 37) -> (-0.8, 37)
  line L14 (1.4, 45) -> (1.4, 37)
  line L15 (-0.8, 45) -> (1.4, 45)
  line L16 (-0.8, 37) -> (-0.8, 45)
extrude "Extrude13" cut sketch "Battery strap passages profiles" along normal blind 3
sketch "All chassis M3 clearances profile" plane through (0, 0, 0) normal (0, 0, 1) x axis (1, 0, 0)
  circle C1 centre (-26, -42) radius 1.7
  circle C2 centre (-26, -22) radius 1.7
  circle C3 centre (26, -42) radius 1.7
  circle C4 centre (26, -22) radius 1.7
  circle C5 centre (-28, -49) radius 1.7
  circle C6 centre (28, -49) radius 1.7
  circle C7 centre (2, 52) radius 1.7
  circle C8 centre (2, 60) radius 1.7
  circle C9 centre (-12, -45) radius 1.7
  circle C10 centre (12, -45) radius 1.7
extrude "Extrude14" cut sketch "All chassis M3 clearances profile" along normal blind 3
sketch "Front diamond opening outline" plane through (0, 0, 0) normal (0, 0, 1) x axis (1, 0, 0)
  line L1 (0, -42) -> (-5, -37)
  line L2 (5, -37) -> (0, -42)
  line L3 (5, -29) -> (5, -37)
  line L4 (0, -24) -> (5, -29)
  line L5 (-5, -29) -> (0, -24)
  line L6 (-5, -37) -> (-5, -29)
extrude "Extrude15" cut sketch "Front diamond opening outline" along normal blind 3
work_plane "WorkPlane5" AlongDistance 3 ExtraOffset 0
sketch "Carrier locating walls profiles" plane through (0, 0, 3) normal (0, 0, 1) x axis (1, 0, 0)
  line L1 (38, -15.4) -> (4.1, -15.4)
  line L2 (38, -13.4) -> (38, -15.4)
  line L3 (4.1, -13.4) -> (38, -13.4)
  line L4 (4.1, -15.4) -> (4.1, -13.4)
  line L5 (6.1, -13.4) -> (4.1, -13.4)
  line L6 (6.1, 46) -> (6.1, -13.4)
  line L7 (4.1, 46) -> (6.1, 46)
  line L8 (4.1, -13.4) -> (4.1, 46)
  line L9 (6.1, 65) -> (4.1, 65)
  line L10 (6.1, 69.4) -> (6.1, 65)
  line L11 (4.1, 69.4) -> (6.1, 69.4)
  line L12 (4.1, 65) -> (4.1, 69.4)
  line L13 (38.9, 69.4) -> (4.1, 69.4)
  line L14 (38.9, 71.4) -> (38.9, 69.4)
  line L15 (4.1, 71.4) -> (38.9, 71.4)
  line L16 (4.1, 69.4) -> (4.1, 71.4)
extrude "Extrude16" add sketch "Carrier locating walls profiles" along normal blind 5.4
work_plane "WorkPlane6" AlongDistance 3 ExtraOffset 0
sketch "Swept starboard bay wall outline" plane through (0, 0, 3) normal (0, 0, 1) x axis (1, 0, 0)
  line L1 (40.9, -8) -> (38.9, -11)
  line L2 (40.9, 67.4) -> (40.9, -8)
  line L3 (38.9, 69.4) -> (40.9, 67.4)
  line L4 (38.9, -11) -> (38.9, 69.4)
extrude "Extrude17" add sketch "Swept starboard bay wall outline" along normal blind 5.4
work_plane "WorkPlane7" AlongDistance 3 ExtraOffset 0
sketch "Four integral corner seats" plane through (0, 0, 3) normal (0, 0, 1) x axis (1, 0, 0)
  circle C1 centre (9.5, -10) radius 3.2
  circle C2 centre (35.5, -10) radius 3.2
  circle C3 centre (9.5, 66) radius 3.2
  circle C4 centre (35.5, 66) radius 3.2
extrude "Extrude18" add sketch "Four integral corner seats" along normal blind 3
work_plane "WorkPlane8" AlongDistance 3 ExtraOffset 0
sketch "Corner seat buttresses profiles" plane through (0, 0, 3) normal (0, 0, 1) x axis (1, 0, 0)
  line L1 (9.5, -12) -> (4.1, -12)
  line L2 (9.5, -8) -> (9.5, -12)
  line L3 (4.1, -8) -> (9.5, -8)
  line L4 (4.1, -12) -> (4.1, -8)
  line L5 (38.7, -11) -> (35.5, -11)
  line L6 (38.7, -8) -> (38.7, -11)
  line L7 (35.5, -8) -> (38.7, -8)
  line L8 (35.5, -11) -> (35.5, -8)
  line L9 (9.5, 64.5) -> (4.1, 64.5)
  line L10 (9.5, 68) -> (9.5, 64.5)
  line L11 (4.1, 68) -> (9.5, 68)
  line L12 (4.1, 64.5) -> (4.1, 68)
  line L13 (40.7, 64) -> (35.5, 64)
  line L14 (40.7, 68) -> (40.7, 64)
  line L15 (35.5, 68) -> (40.7, 68)
  line L16 (35.5, 64) -> (35.5, 68)
extrude "Extrude19" add sketch "Corner seat buttresses profiles" along normal blind 1.5
sketch "Carrier M3 clearance bores profile" plane through (0, 0, 0) normal (0, 0, 1) x axis (1, 0, 0)
  circle C1 centre (9.5, -10) radius 1.7
  circle C2 centre (35.5, -10) radius 1.7
  circle C3 centre (9.5, 66) radius 1.7
  circle C4 centre (35.5, 66) radius 1.7
extrude "Extrude20" cut sketch "Carrier M3 clearance bores profile" along normal blind 6
sketch "Underside M3 captive nut pockets profiles" plane through (0, 0, 0) normal (0, 0, 1) x axis (1, 0, 0)
  line L1 (11.1743, -7.1) -> (12.8486, -10)
  line L2 (7.8257, -7.1) -> (11.1743, -7.1)
  line L3 (6.1514, -10) -> (7.8257, -7.1)
  line L4 (7.8257, -12.9) -> (6.1514, -10)
  line L5 (11.1743, -12.9) -> (7.8257, -12.9)
  line L6 (12.8486, -10) -> (11.1743, -12.9)
  line L7 (37.1743, -7.1) -> (38.8486, -10)
  line L8 (33.8257, -7.1) -> (37.1743, -7.1)
  line L9 (32.1514, -10) -> (33.8257, -7.1)
  line L10 (33.8257, -12.9) -> (32.1514, -10)
  line L11 (37.1743, -12.9) -> (33.8257, -12.9)
  line L12 (38.8486, -10) -> (37.1743, -12.9)
  line L13 (11.1743, 68.9) -> (12.8486, 66)
  line L14 (7.8257, 68.9) -> (11.1743, 68.9)
  line L15 (6.1514, 66) -> (7.8257, 68.9)
  line L16 (7.8257, 63.1) -> (6.1514, 66)
  line L17 (11.1743, 63.1) -> (7.8257, 63.1)
  line L18 (12.8486, 66) -> (11.1743, 63.1)
  line L19 (37.1743, 68.9) -> (38.8486, 66)
  line L20 (33.8257, 68.9) -> (37.1743, 68.9)
  line L21 (32.1514, 66) -> (33.8257, 68.9)
  line L22 (33.8257, 63.1) -> (32.1514, 66)
  line L23 (37.1743, 63.1) -> (33.8257, 63.1)
  line L24 (38.8486, 66) -> (37.1743, 63.1)
extrude "Extrude21" cut sketch "Underside M3 captive nut pockets profiles" along normal blind 2.6
work_plane "WorkPlane9" AlongDistance 6.5 ExtraOffset 0
sketch "USB C side plug opening profile" plane through (0, 0, 6.5) normal (0, 0, 1) x axis (1, 0, 0)
  line L1 (42, 4.4) -> (38.8, 4.4)
  line L2 (42, 17.6) -> (42, 4.4)
  line L3 (38.8, 17.6) -> (42, 17.6)
  line L4 (38.8, 4.4) -> (38.8, 17.6)
extrude "Extrude22" cut sketch "USB C side plug opening profile" along normal blind 3
work_plane "WorkPlane10" AlongDistance 7.4 ExtraOffset 0
sketch "Programming USB rear scallop profile" plane through (0, 0, 7.4) normal (0, 0, 1) x axis (1, 0, 0)
  line L1 (30.5, 69.2) -> (16.5, 69.2)
  line L2 (30.5, 71.6) -> (30.5, 69.2)
  line L3 (16.5, 71.6) -> (30.5, 71.6)
  line L4 (16.5, 69.2) -> (16.5, 71.6)
extrude "Extrude23" cut sketch "Programming USB rear scallop profile" along normal blind 1.2
work_plane "WorkPlane11" AlongDistance 4.5 ExtraOffset 0
sketch "Motor wire exits profiles" plane through (0, 0, 4.5) normal (0, 0, 1) x axis (1, 0, 0)
  line L1 (18, -15.6) -> (8, -15.6)
  line L2 (18, -13.2) -> (18, -15.6)
  line L3 (8, -13.2) -> (18, -13.2)
  line L4 (8, -15.6) -> (8, -13.2)
  line L5 (36, -15.6) -> (27, -15.6)
  line L6 (36, -13.2) -> (36, -15.6)
  line L7 (27, -13.2) -> (36, -13.2)
  line L8 (27, -15.6) -> (27, -13.2)
extrude "Extrude24" cut sketch "Motor wire exits profiles" along normal blind 4
work_plane "WorkPlane12" AlongDistance 4.4 ExtraOffset 0
sketch "Battery and RUN wire exits profiles" plane through (0, 0, 4.4) normal (0, 0, 1) x axis (1, 0, 0)
  line L1 (6.3, 2) -> (3.9, 2)
  line L2 (6.3, 9) -> (6.3, 2)
  line L3 (3.9, 9) -> (6.3, 9)
  line L4 (3.9, 2) -> (3.9, 9)
  line L5 (6.3, 31) -> (3.9, 31)
  line L6 (6.3, 39) -> (6.3, 31)
  line L7 (3.9, 39) -> (6.3, 39)
  line L8 (3.9, 31) -> (3.9, 39)
extrude "Extrude25" cut sketch "Battery and RUN wire exits profiles" along normal blind 4.2
work_plane "WorkPlane13" AlongDistance 2 ExtraOffset 0
sketch "Central recessed wire channel profile" plane through (0, 0, 2) normal (0, 0, 1) x axis (1, 0, 0)
  line L1 (3.6, -13) -> (1.5, -13)
  line L2 (3.6, 46) -> (3.6, -13)
  line L3 (1.5, 46) -> (3.6, 46)
  line L4 (1.5, -13) -> (1.5, 46)
extrude "Extrude26" cut sketch "Central recessed wire channel profile" along normal blind 1
work_plane "WorkPlane14" AlongDistance 3 ExtraOffset 0
sketch "Tail screw driver access relief profile" plane through (0, 0, 3) normal (0, 0, 1) x axis (1, 0, 0)
  circle C1 centre (2, 52) radius 4.25
  circle C2 centre (2, 60) radius 4.25
extrude "Extrude27" cut sketch "Tail screw driver access relief profile" along normal blind 6
work_plane "WorkPlane15" AlongDistance 3.8 ExtraOffset 0
sketch "Starboard sculpted gill 1 outline" plane through (0, 0, 3.8) normal (0, 0, 1) x axis (1, 0, 0)
  line L1 (41.2, 23) -> (40.05, 24.5)
  line L2 (41.2, 28) -> (41.2, 23)
  line L3 (40.05, 29.5) -> (41.2, 28)
  line L4 (40.05, 24.5) -> (40.05, 29.5)
extrude "Extrude28" cut sketch "Starboard sculpted gill 1 outline" along normal blind 3
work_plane "WorkPlane16" AlongDistance 3.8 ExtraOffset 0
sketch "Starboard sculpted gill 2 outline" plane through (0, 0, 3.8) normal (0, 0, 1) x axis (1, 0, 0)
  line L1 (41.2, 34) -> (40.05, 35.5)
  line L2 (41.2, 39) -> (41.2, 34)
  line L3 (40.05, 40.5) -> (41.2, 39)
  line L4 (40.05, 35.5) -> (40.05, 40.5)
extrude "Extrude29" cut sketch "Starboard sculpted gill 2 outline" along normal blind 3
work_plane "WorkPlane17" AlongDistance 3.8 ExtraOffset 0
sketch "Starboard sculpted gill 3 outline" plane through (0, 0, 3.8) normal (0, 0, 1) x axis (1, 0, 0)
  line L1 (41.2, 45) -> (40.05, 46.5)
  line L2 (41.2, 50) -> (41.2, 45)
  line L3 (40.05, 51.5) -> (41.2, 50)
  line L4 (40.05, 46.5) -> (40.05, 51.5)
extrude "Extrude30" cut sketch "Starboard sculpted gill 3 outline" along normal blind 3
work_plane "WorkPlane18" AlongDistance 3.8 ExtraOffset 0
sketch "Starboard sculpted gill 4 outline" plane through (0, 0, 3.8) normal (0, 0, 1) x axis (1, 0, 0)
  line L1 (41.2, 56) -> (40.05, 57.5)
  line L2 (41.2, 61) -> (41.2, 56)
  line L3 (40.05, 62.5) -> (41.2, 61)
  line L4 (40.05, 57.5) -> (40.05, 62.5)
extrude "Extrude31" cut sketch "Starboard sculpted gill 4 outline" along normal blind 3
work_plane "WorkPlane19" AlongDistance 3 ExtraOffset 0
sketch "SCOUT marking" plane through (0, 0, 3) normal (0, 0, 1) x axis (1, 0, 0)
  dimension "d1488" = 2.8
extrude "Extrude32" cut sketch "SCOUT marking" against normal blind 0.35
sketch "M3 clamp through clearance profile" plane through (0, 0, 0) normal (0, 0, 1) x axis (1, 0, 0)
  circle C1 centre (0, -10) radius 1.7
  circle C2 centre (0, 10) radius 1.7
extrude "Extrude8" cut sketch "M3 clamp through clearance profile" along normal blind 12.8
work_plane "WorkPlane4" AlongDistance 9.6 ExtraOffset 0
sketch "M3 cap head pockets 6.2 x 3.2 profile" plane through (0, 0, 9.6) normal (0, 0, 1) x axis (1, 0, 0)
  circle C1 centre (0, -10) radius 3.1
  circle C2 centre (0, 10) radius 3.1
extrude "Extrude9" cut sketch "M3 cap head pockets 6.2 x 3.2 profile" along normal blind 3.2
sketch "M3 clamp through clearance profile" plane through (0, 0, 0) normal (0, 0, 1) x axis (1, 0, 0)
  circle C1 centre (0, -10) radius 1.7
  circle C2 centre (0, 10) radius 1.7
extrude "Extrude8" cut sketch "M3 clamp through clearance profile" along normal blind 12.8
work_plane "WorkPlane4" AlongDistance 9.6 ExtraOffset 0
sketch "M3 cap head pockets 6.2 x 3.2 profile" plane through (0, 0, 9.6) normal (0, 0, 1) x axis (1, 0, 0)
  circle C1 centre (0, -10) radius 3.1
  circle C2 centre (0, 10) radius 3.1
extrude "Extrude9" cut sketch "M3 cap head pockets 6.2 x 3.2 profile" along normal blind 3.2
sketch "M3 bumper clearance revised profile" plane through (0, 0, 0) normal (0, 0, 1) x axis (1, 0, 0)
  circle C1 centre (-28, -49) radius 1.7
  circle C2 centre (28, -49) radius 1.7
extrude "Extrude11" cut sketch "M3 bumper clearance revised profile" along normal blind 6
work_plane "WorkPlane7" AlongDistance 3 ExtraOffset 0
sketch "M3 cap head bumper pockets profile" plane through (0, 0, 3) normal (0, 0, 1) x axis (1, 0, 0)
  circle C1 centre (-28, -49) radius 3.1
  circle C2 centre (28, -49) radius 3.1
extrude "Extrude12" cut sketch "M3 cap head bumper pockets profile" along normal blind 3
sketch "M3 revised skid bores" plane through (0, 0, 0) normal (0, 1, 0) x axis (1, 0, 0)
  circle C1 centre (52, -6) radius 1.7
  circle C2 centre (60, -6) radius 1.7
extrude "Extrude4" cut sketch "M3 revised skid bores" along a picked direction blind -4 (= "-( 4 mm )")
sketch "Rear bay floor continuous print support outline" plane through (0, 0, 0) normal (0, 0, 1) x axis (1, 0, 0)
  line L1 (36.9, 70.9) -> (3.8, 69)
  line L2 (36.9, 71.4) -> (36.9, 70.9)
  line L3 (4.1, 71.4) -> (36.9, 71.4)
  line L4 (3.8, 71.1) -> (4.1, 71.4)
  line L5 (3.8, 69) -> (3.8, 71.1)
extrude "Extrude33" add sketch "Rear bay floor continuous print support outline" along normal blind 3
work_plane "WorkPlane20" AlongDistance 3 ExtraOffset 0
sketch "Rear wall follows chassis bevel outline" plane through (0, 0, 3) normal (0, 0, 1) x axis (1, 0, 0)
  line L1 (39.1, 69.4) -> (38.9, 69.4)
  line L2 (39.1, 71.6) -> (39.1, 69.4)
  line L3 (36.7, 71.6) -> (39.1, 71.6)
  line L4 (38.9, 69.4) -> (36.7, 71.6)
extrude "Extrude34" cut sketch "Rear wall follows chassis bevel outline" along normal blind 6
sketch "Chamfered FR4 outline outline" plane through (0, 0, 0) normal (0, 0, 1) x axis (1, 0, 0)
  line L1 (30, 0) -> (2, 0)
  line L2 (32, 2) -> (30, 0)
  line L3 (32, 80) -> (32, 2)
  line L4 (30, 82) -> (32, 80)
  line L5 (2, 82) -> (30, 82)
  line L6 (0, 80) -> (2, 82)
  line L7 (0, 2) -> (0, 80)
  line L8 (2, 0) -> (0, 2)
extrude "Extrude1" new body sketch "Chamfered FR4 outline outline" along normal blind 1.6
